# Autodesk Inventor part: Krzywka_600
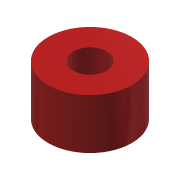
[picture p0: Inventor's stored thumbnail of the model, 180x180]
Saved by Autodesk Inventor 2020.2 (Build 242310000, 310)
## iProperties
Created: 2014-12
Part Number: Krzywka_600
Material: Ogólny
Document SubType Name: Modeling
Designer: F.Stasiak
Density: 1 g/cm^3
Appearance: Jasnoczerwona
Mass: 6.18501 g
Surface Area: 24.74 cm^2
Volume: 6.18501 cm^3
Catalog Web Link: www.expertbooks.pl
Manager: www.cadconsulting.pl
Company: Fabian Stasiak CAD Consulting
Author: F.Stasiak
Subject: Zbiór ćwiczeń. Autodesk Inventor 2020. Kurs Professional
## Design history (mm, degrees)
sketch "Szkic1"
  geometry: C1 r 5 at (0, 0); C2 r 12.5 at (0, 0); 1 further point
  constraints: 2 centre point, 2 coincident
  dimensions: "d0" = 10 diameter of C1; "d1" = 25 diameter of C2
extrude "Wyciągnięcie proste1" new body sketch "Szkic1" distance "d2" = 15; taper "d3" = 0 deg
node "Bryła1"
